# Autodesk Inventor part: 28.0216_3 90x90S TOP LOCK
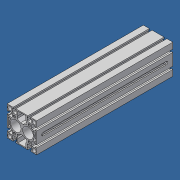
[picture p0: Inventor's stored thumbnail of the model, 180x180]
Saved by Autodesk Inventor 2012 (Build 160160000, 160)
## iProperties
Created: 2011-05
Part Number: 28.0216_3 90x90S TOP LOCK
Material: Aluminum-6061
Description: PROFILE 90X90 S
Document SubType Name: Modeling
Designer: Administrator
Stock Number: 20.1019
Density: 2.71 g/cm^3
Author: Administrator
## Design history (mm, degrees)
sketch "Sketch1"
  geometry: L1 (-31.7, -15.7)-(-40.5, -15.7) reference; L2 (-40.5, -15.7)-(-40.5, -18.25) reference; L3 (-40.5, -18.25)-(-45, -18.25) reference; L4 (-45, -18.25)-(-45, 18.25) reference; L5 (-45, 18.25)-(-40.5, 18.25) reference; L6 (-40.5, 18.25)-(-40.5, 15.7) reference; L7 (-40.5, 15.7)-(-31.7, 15.7) reference; L8 (-31.7, 15.7)-(-29.7, 17.7) reference; L9 (-29.7, 17.7)-(-29.7, 27.3) reference; L10 (-29.7, 27.3)-(-31.7, 29.3) reference; L11 (-31.7, 29.3)-(-40.5, 29.3) reference; L12 (-40.5, 29.3)-(-40.5, 26.75) reference; L13 (-40.5, 26.75)-(-45, 26.75) reference; L14 (-45, 26.75)-(-45, 45) reference; L15 (29.3, 31.7)-(29.3, 40.5) reference; L16 (-26.75, 45)-(-26.75, 40.5) reference; L17 (-26.75, 40.5)-(-29.3, 40.5) reference; L18 (-29.3, 40.5)-(-29.3, 31.7) reference; L19 (-29.3, 31.7)-(-27.3, 29.7) reference; L20 (-27.3, 29.7)-(-17.7, 29.7) reference; L21 (-17.7, 29.7)-(-15.7, 31.7) reference; L22 (-15.7, 31.7)-(-15.7, 40.5) reference; L23 (-15.7, 40.5)-(-18.25, 40.5) reference; L24 (-18.25, 40.5)-(-18.25, 45) reference; L25 (-18.25, 45)-(18.25, 45) reference; L26 (18.25, 45)-(18.25, 40.5) reference; L27 (18.25, 40.5)-(15.7, 40.5) reference; L28 (15.7, 40.5)-(15.7, 31.7) reference; L29 (15.7, 31.7)-(17.7, 29.7) reference; L30 (17.7, 29.7)-(27.3, 29.7) reference; L31 (27.3, 29.7)-(29.3, 31.7) reference; L32 (29.3, 40.5)-(26.75, 40.5) reference; L33 (26.75, 40.5)-(26.75, 45) reference; L34 (26.75, 45)-(45, 45) reference; L35 (45, 45)-(45, 26.75) reference; L36 (45, 26.75)-(40.5, 26.75) reference; L37 (40.5, 26.75)-(40.5, 29.3) reference; L38 (40.5, 29.3)-(31.7, 29.3) reference; L39 (31.7, 29.3)-(29.7, 27.3) reference; L40 (29.7, 27.3)-(29.7, 17.7) reference; L41 (29.7, 17.7)-(31.7, 15.7) reference; L42 (31.7, 15.7)-(40.5, 15.7) reference; L43 (40.5, 15.7)-(40.5, 18.25) reference; L44 (40.5, 18.25)-(45, 18.25) reference; L45 (45, 18.25)-(45, -18.25) reference; L46 (45, -18.25)-(40.5, -18.25) reference; L47 (40.5, -18.25)-(40.5, -15.7) reference; L48 (40.5, -15.7)-(31.7, -15.7) reference; L49 (31.7, -15.7)-(29.7, -17.7) reference; L50 (29.7, -17.7)-(29.7, -27.3) reference; L51 (29.7, -27.3)-(31.7, -29.3) reference; L52 (31.7, -29.3)-(40.5, -29.3) reference; L53 (40.5, -29.3)-(40.5, -26.75) reference; L54 (40.5, -26.75)-(45, -26.75) reference; L55 (45, -26.75)-(45, -45) reference; L56 (45, -45)-(26.75, -45) reference; L57 (26.75, -45)-(26.75, -40.5) reference; L58 (26.75, -40.5)-(29.3, -40.5) reference; L59 (29.3, -40.5)-(29.3, -31.7) reference; L60 (29.3, -31.7)-(27.3, -29.7) reference; L61 (27.3, -29.7)-(17.7, -29.7) reference; L62 (17.7, -29.7)-(15.7, -31.7) reference; L63 (15.7, -31.7)-(15.7, -40.5) reference; L64 (15.7, -40.5)-(18.25, -40.5) reference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; C1 r 3.75 at (22.5, -22.5) reference; C2 r 5.85 at (37.15, 37.15) reference; C3 r 5.85 at (-37.15, 37.15) reference; C4 r 5.85 at (-37.15, -37.15) reference; C5 r 5.85 at (37.15, -37.15) reference; C6 r 3.75 at (-22.5, 22.5) reference; C7 r 3.75 at (-22.5, -22.5) reference; C8 r 3.75 at (22.5, 22.5) reference; C9 r 16 at (18.5, 0) reference; C10 r 16 at (-18.5, 0) reference; A1 r 19 centre (18.5, 0) between (33.47, -11.7) and (33.47, 11.7) reference; A2 r 19 centre (-18.5, 0) between (-33.47, 11.7) and (-33.47, -11.7) reference
  constraints: 228 end point, 17 horizontal, 17 vertical, 12 centre point, 4 point on circle, 2 midpoint, 2 point on line, 222 other
extrude "Extrusion1" new body sketch "Sketch1" stored distance "d0" = 414.8 (computed from TRAVEL); taper "d1" = 0 deg
sketch "Sketch2"
  geometry: L1 (0, 36.5)-(0, 0) reference; L2 (414.8, 0)-(414.8, 36.5) reference; L3 (20, 23)-(394.8, 23); L4 (394.8, 13.5)-(20, 13.5); A1 r 4.75 centre (20, 18.25) between (20, 23) and (20, 13.5); A2 r 4.75 centre (394.8, 18.25) between (394.8, 13.5) and (394.8, 23); 3 further points
  constraints: 6 point on circle, 4 end point, 4 tangent, 2 centre point, 2 horizontal alignment, 2 midpoint, 2 point on line, 1 equal radius
  dimensions: "d2" = 20 distance from line of A1.centre L1 (= d3); "d3" = 20 distance from line of A2.centre L2; "d4" = 4.75 radius of A1
extrude "Extrusion2" cut sketch "Sketch2" distance "d5" = 15.875; taper "d6" = 0 deg
thread "Thread1" dims "d7" = 25.4, "d8" = 0
thread "Thread2" dims "d9" = 25.4, "d10" = 0
thread "Thread3" dims "d11" = 25.4, "d12" = 0
thread "Thread4" dims "d13" = 25.4, "d14" = 0
thread "Thread5" dims "d15" = 25.4, "d16" = 0
thread "Thread6" dims "d17" = 25.4, "d18" = 0
thread "Thread7" dims "d19" = 25.4, "d20" = 0
thread "Thread8" dims "d21" = 25.4, "d22" = 0
body "Solid1"
other parameters: "TRAVEL" = 304.8 [user parameter; used in 1 equation term]
